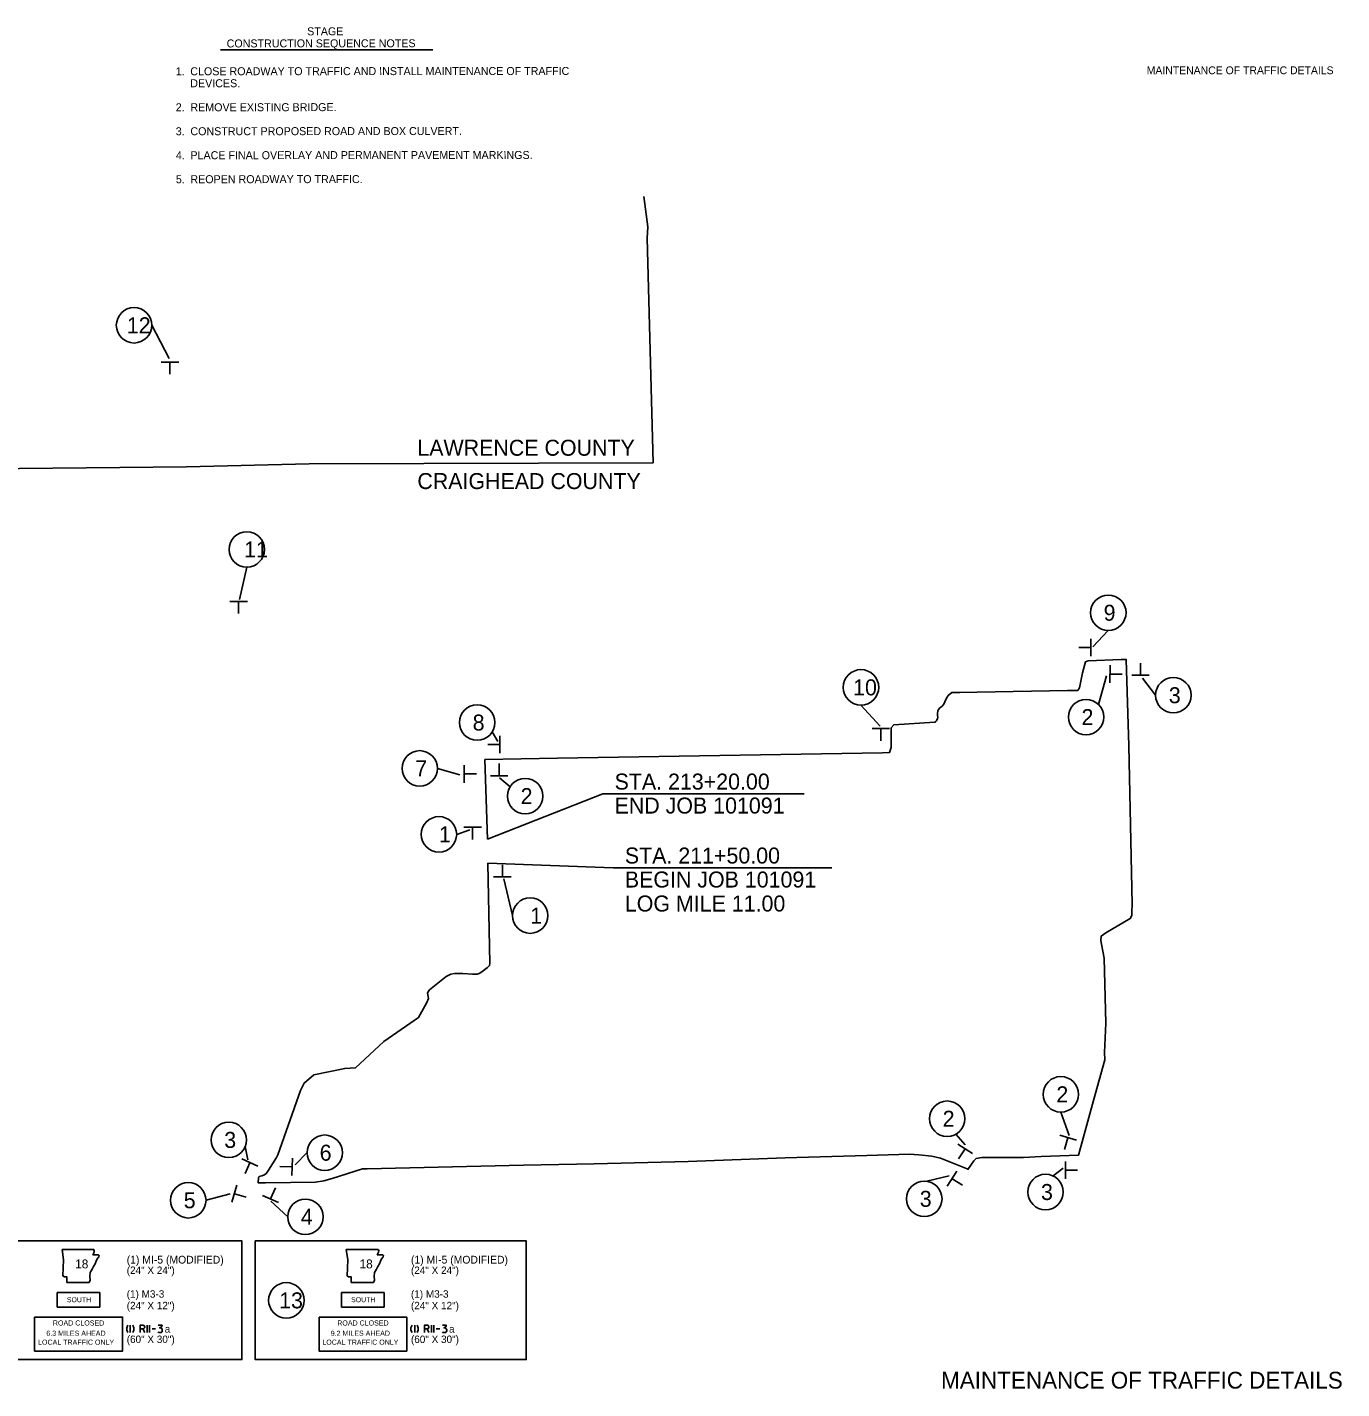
# Model space of a CAD drawing. Extents: x -31818 to 1228740, y -23925 to 152440.
# Drawn here: x -31762.5 to -31663.9, y -23925.5 to -23823.3 of the extents above; entities that cross this region are included whole.
import ezdxf

# ---------------------------------------------------------------- set-up
doc = ezdxf.new("R2010")
doc.units = 0
for name, color, linetype in [('2', 7, 'Continuous'), ('21', 7, 'Continuous'), ('3', 7, 'Continuous'), ('38', 7, 'Continuous'), ('53', 7, 'Continuous'), ('59', 7, 'Continuous'), ('8', 7, 'Continuous'), ('Level 1', 7, 'Continuous'), ('Level 3', 7, 'Continuous'), ('Level 8', 7, 'Continuous'), ('shading', 7, 'Continuous')]:
    doc.layers.add(name, color=color, linetype=linetype)

msp = doc.modelspace()

# ---------------------------------------------------------------- linework, layer by layer
at = {"layer": '21'}
for points in [[(-31759.89, -23915.04), (-31759.78, -23915.83), (-31759.83, -23917.03), (-31759.72, -23917.1), (-31759.53, -23917.1), (-31759.53, -23917.52), (-31757.86, -23917.52), (-31757.78, -23917.35), (-31757.81, -23917.07), (-31757.77, -23916.76), (-31757.63, -23916.51), (-31757.53, -23916.32), (-31757.4, -23916.12), (-31757.32, -23915.91), (-31757.25, -23915.74), (-31757.14, -23915.6), (-31757.11, -23915.5), (-31757.16, -23915.44), (-31757.57, -23915.44), (-31757.48, -23915.25), (-31757.47, -23915.13), (-31757.52, -23915.04)], [(-31738.56, -23915.04), (-31738.44, -23915.83), (-31738.49, -23917.03), (-31738.39, -23917.1), (-31738.19, -23917.1), (-31738.19, -23917.52), (-31736.53, -23917.52), (-31736.45, -23917.35), (-31736.48, -23917.07), (-31736.44, -23916.76), (-31736.29, -23916.51), (-31736.2, -23916.32), (-31736.07, -23916.12), (-31735.99, -23915.91), (-31735.92, -23915.74), (-31735.8, -23915.6), (-31735.77, -23915.5), (-31735.83, -23915.44), (-31736.24, -23915.44), (-31736.14, -23915.25), (-31736.13, -23915.13), (-31736.18, -23915.04)]]:
    msp.add_lwpolyline(points, close=True, dxfattribs=at)
at = {"layer": '53'}
for p, q in [((-31748, -23825.03), (-31732.07, -23825.03)), ((-31727.97, -23884.24), (-31719.32, -23880.86)), ((-31719.32, -23880.86), (-31704.2, -23880.86)), ((-31727.93, -23886.06), (-31718.54, -23886.41)), ((-31718.54, -23886.41), (-31702.12, -23886.41))]:
    msp.add_line(p, q, dxfattribs=at)
at = {"layer": '59'}
for p, q in [((-31757.05, -23918.27), (-31760.25, -23918.27)), ((-31760.25, -23918.27), (-31760.25, -23919.36)), ((-31757.05, -23918.27), (-31757.05, -23919.36)), ((-31735.71, -23918.27), (-31738.91, -23918.27)), ((-31738.91, -23918.27), (-31738.91, -23919.36)), ((-31735.71, -23918.27), (-31735.71, -23919.36)), ((-31757.05, -23919.36), (-31760.25, -23919.36)), ((-31735.71, -23919.36), (-31738.91, -23919.36))]:
    msp.add_line(p, q, dxfattribs=at)
at = {"layer": '8'}
for p, q in [((-31753.15, -23845.69), (-31751.86, -23848.18)), ((-31746.03, -23863.85), (-31746.57, -23866.27)), ((-31681.38, -23868.59), (-31682.54, -23869.81)), ((-31682.11, -23874.15), (-31681.52, -23872)), ((-31677.83, -23873.45), (-31678.82, -23872.17)), ((-31699.94, -23874.19), (-31698.49, -23875.78)), ((-31727.61, -23876.21), (-31727.18, -23876.92)), ((-31731.71, -23878.94), (-31730.05, -23879.42)), ((-31726.27, -23880.32), (-31727.06, -23879.64)), ((-31730.27, -23883.89), (-31729.28, -23883.55)), ((-31726.09, -23889.99), (-31726.74, -23887.24)), ((-31684.94, -23904.73), (-31684.31, -23906.49)), ((-31692.81, -23906.39), (-31692.12, -23907.18)), ((-31746.14, -23907.32), (-31745.95, -23908.31)), ((-31741.52, -23907.78), (-31742.41, -23908.68)), ((-31685.53, -23909.52), (-31684.76, -23908.93)), ((-31695, -23909.92), (-31693.33, -23909.51)), ((-31749.09, -23911.35), (-31747.27, -23910.87)), ((-31742.96, -23912.59), (-31744.23, -23911.42))]:
    msp.add_line(p, q, dxfattribs=at)
for points in [[(-31787.28, -23856.65), (-31787.2, -23856.65), (-31787.2, -23856.65), (-31782.9, -23856.63), (-31778.14, -23856.59), (-31750.55, -23856.3), (-31741.34, -23856.09), (-31715.54, -23856), (-31715.99, -23839.15), (-31715.94, -23838.29), (-31716.23, -23836.03)], [(-31727.93, -23886.06), (-31727.8, -23893.59), (-31727.82, -23893.72), (-31727.97, -23893.87), (-31728.4, -23894.21), (-31728.6, -23894.33), (-31728.75, -23894.37), (-31729.09, -23894.38), (-31729.81, -23894.34), (-31730.19, -23894.32), (-31730.44, -23894.32), (-31730.71, -23894.37), (-31731.07, -23894.56), (-31732.33, -23895.56), (-31732.47, -23895.78), (-31732.4, -23896.21), (-31732.52, -23896.5), (-31733.14, -23897.63), (-31735.74, -23899.44), (-31737.88, -23901.41), (-31738.68, -23901.45), (-31741, -23901.94), (-31741.72, -23902.55), (-31742, -23903.11), (-31743.71, -23907.94), (-31743.8, -23908.13), (-31744.4, -23909.1), (-31744.55, -23909.32), (-31744.69, -23909.45), (-31744.9, -23909.51), (-31745.1, -23909.57), (-31745.15, -23909.67), (-31745.18, -23910.04), (-31744.63, -23910.04), (-31740.87, -23909.98), (-31740.25, -23909.88), (-31739.63, -23909.72), (-31737.35, -23908.98), (-31737, -23908.98), (-31725.27, -23908.72), (-31719.95, -23908.62), (-31712.9, -23908.44), (-31705.62, -23908.16), (-31699.51, -23907.98), (-31696.31, -23907.88), (-31695.61, -23907.94), (-31694.63, -23908.05), (-31693.98, -23908.2), (-31691.96, -23909), (-31691.91, -23909.04), (-31691.46, -23908.39), (-31691.3, -23908.21), (-31690.86, -23908.13), (-31687.75, -23908.15), (-31686.43, -23908.07), (-31683.61, -23907.96), (-31682.49, -23903.86), (-31681.65, -23900.8), (-31681.66, -23900.25), (-31681.56, -23898.07), (-31681.7, -23893.18), (-31681.89, -23892.12), (-31681.93, -23891.85), (-31681.91, -23891.53), (-31681.56, -23891.28), (-31679.74, -23890.21), (-31679.62, -23889.97), (-31679.62, -23889.73), (-31679.59, -23889.12), (-31679.85, -23877.26), (-31680.03, -23870.76), (-31680.42, -23870.78), (-31682.88, -23870.87), (-31683.09, -23870.94), (-31683.31, -23871.76), (-31683.55, -23872.9), (-31683.67, -23873.09), (-31684.44, -23873.09), (-31691.22, -23873.21), (-31692.51, -23873.25), (-31693.12, -23873.25), (-31693.39, -23873.48), (-31693.52, -23873.68), (-31693.66, -23873.94), (-31693.72, -23874.12), (-31693.86, -23874.27), (-31694.05, -23874.41), (-31694.16, -23874.56), (-31694.17, -23874.62), (-31694.2, -23874.81), (-31694.19, -23874.9), (-31694.19, -23874.98), (-31694.18, -23875.1), (-31694.21, -23875.23), (-31694.24, -23875.3), (-31694.27, -23875.37), (-31694.35, -23875.45), (-31694.39, -23875.48), (-31697.48, -23875.67), (-31697.67, -23875.89), (-31697.68, -23877.38), (-31697.81, -23877.76), (-31698.33, -23877.77), (-31707.49, -23877.92), (-31722.71, -23878.18), (-31728.16, -23878.28), (-31727.97, -23884.24)]]:
    msp.add_lwpolyline(points, dxfattribs=at)
for points in [[(-31766.73, -23914.4), (-31746.4, -23914.4), (-31746.4, -23923.31), (-31766.73, -23923.31)], [(-31745.4, -23914.4), (-31725.06, -23914.4), (-31725.06, -23923.31), (-31745.4, -23923.31)]]:
    msp.add_lwpolyline(points, close=True, dxfattribs=at)
at = {"layer": 'Level 1'}
for points in [[(-31761.95, -23920.11), (-31755.35, -23920.11), (-31755.35, -23922.67), (-31761.95, -23922.67)], [(-31740.61, -23920.11), (-31734.02, -23920.11), (-31734.02, -23922.67), (-31740.61, -23922.67)]]:
    msp.add_lwpolyline(points, close=True, dxfattribs=at)
at = {"layer": 'Level 3'}
for p, q in [((-31752.45, -23848.45), (-31751.14, -23848.45)), ((-31751.8, -23848.47), (-31751.8, -23849.36)), ((-31747.29, -23866.41), (-31745.98, -23866.41)), ((-31746.64, -23866.43), (-31746.64, -23867.32)), ((-31682.71, -23869.87), (-31683.6, -23869.87)), ((-31682.69, -23869.22), (-31682.69, -23870.53)), ((-31681.26, -23872.51), (-31681.25, -23871.2)), ((-31678.96, -23871.93), (-31678.96, -23871.04)), ((-31681.24, -23871.86), (-31680.34, -23871.86)), ((-31678.31, -23871.95), (-31679.62, -23871.95)), ((-31699.11, -23875.95), (-31697.8, -23875.95)), ((-31698.46, -23875.97), (-31698.46, -23876.87)), ((-31727.05, -23877.14), (-31727.95, -23877.14)), ((-31727.03, -23876.49), (-31727.03, -23877.8)), ((-31729.71, -23880.02), (-31729.72, -23878.7)), ((-31729.69, -23879.36), (-31728.8, -23879.35)), ((-31727.08, -23879.47), (-31727.08, -23878.58)), ((-31726.43, -23879.49), (-31727.74, -23879.49)), ((-31729.73, -23883.35), (-31728.42, -23883.35)), ((-31729.08, -23883.37), (-31729.08, -23884.27)), ((-31726.85, -23887.08), (-31726.85, -23886.18)), ((-31726.2, -23887.09), (-31727.51, -23887.09)), ((-31685.03, -23906.47), (-31683.77, -23906.84)), ((-31684.41, -23906.67), (-31684.66, -23907.53)), ((-31692.67, -23907.13), (-31691.56, -23907.84)), ((-31692.13, -23907.5), (-31692.61, -23908.25)), ((-31746.39, -23908.25), (-31745.19, -23908.78)), ((-31745.8, -23908.53), (-31746.16, -23909.35)), ((-31742.64, -23908.83), (-31743.54, -23908.81)), ((-31742.61, -23908.18), (-31742.64, -23909.49)), ((-31684.6, -23909.74), (-31684.6, -23908.43)), ((-31693.46, -23910.28), (-31692.75, -23909.17)), ((-31693.09, -23909.74), (-31692.33, -23910.22)), ((-31684.58, -23909.09), (-31683.69, -23909.09)), ((-31747.15, -23911.48), (-31746.77, -23910.22)), ((-31746.94, -23910.86), (-31746.08, -23911.12)), ((-31743.65, -23911.52), (-31744.85, -23910.99)), ((-31744.24, -23911.24), (-31743.88, -23910.42))]:
    msp.add_line(p, q, dxfattribs=at)
at = {"layer": 'Level 8'}
for p, q in [((-31754.77, -23921.28), (-31754.77, -23920.73)), ((-31753.82, -23921), (-31753.69, -23921.28)), ((-31753.51, -23921.28), (-31753.51, -23920.73)), ((-31753.33, -23921.28), (-31753.33, -23920.73)), ((-31753.14, -23921), (-31752.87, -23921)), ((-31733.43, -23921.28), (-31733.43, -23920.73)), ((-31732.49, -23921), (-31732.36, -23921.28)), ((-31732.18, -23921.28), (-31732.18, -23920.73)), ((-31731.99, -23921.28), (-31731.99, -23920.73)), ((-31731.81, -23921), (-31731.54, -23921))]:
    msp.add_line(p, q, dxfattribs=at)
for points in [[(-31754.95, -23920.73), (-31755.04, -23920.91), (-31755.04, -23921.1), (-31754.95, -23921.28)], [(-31754.59, -23920.73), (-31754.5, -23920.91), (-31754.5, -23921.1), (-31754.59, -23921.28)], [(-31754.04, -23921.28), (-31754.04, -23920.73), (-31753.82, -23920.73), (-31753.75, -23920.75), (-31753.69, -23920.84), (-31753.69, -23920.89), (-31753.75, -23920.98), (-31753.82, -23921), (-31754.04, -23921)], [(-31752.69, -23920.73), (-31752.39, -23920.73), (-31752.41, -23920.79), (-31752.44, -23920.84), (-31752.48, -23920.88), (-31752.57, -23920.93), (-31752.51, -23920.93), (-31752.44, -23920.96), (-31752.39, -23921), (-31752.37, -23921.07), (-31752.37, -23921.15), (-31752.39, -23921.22), (-31752.44, -23921.27), (-31752.51, -23921.28), (-31752.58, -23921.28), (-31752.65, -23921.27), (-31752.69, -23921.22)], [(-31733.62, -23920.73), (-31733.71, -23920.91), (-31733.71, -23921.1), (-31733.62, -23921.28)], [(-31733.25, -23920.73), (-31733.16, -23920.91), (-31733.16, -23921.1), (-31733.25, -23921.28)], [(-31732.7, -23921.28), (-31732.7, -23920.73), (-31732.48, -23920.73), (-31732.41, -23920.75), (-31732.36, -23920.84), (-31732.36, -23920.89), (-31732.41, -23920.98), (-31732.48, -23921), (-31732.7, -23921)], [(-31731.35, -23920.73), (-31731.06, -23920.73), (-31731.07, -23920.79), (-31731.1, -23920.84), (-31731.15, -23920.88), (-31731.24, -23920.93), (-31731.17, -23920.93), (-31731.1, -23920.96), (-31731.06, -23921), (-31731.03, -23921.07), (-31731.03, -23921.15), (-31731.06, -23921.22), (-31731.1, -23921.27), (-31731.17, -23921.28), (-31731.25, -23921.28), (-31731.31, -23921.27), (-31731.35, -23921.22)]]:
    msp.add_lwpolyline(points, dxfattribs=at)
for centre in [(-31754.49, -23845.69), (-31746.03, -23862.51), (-31681.38, -23867.26), (-31699.94, -23872.86), (-31676.5, -23873.45), (-31728.74, -23875.5), (-31683.05, -23875.09), (-31733.05, -23878.94), (-31725.14, -23881.02), (-31731.61, -23883.89), (-31724.76, -23889.99), (-31684.94, -23903.4), (-31693.47, -23905.23), (-31747.38, -23906.82), (-31740.18, -23907.78), (-31750.42, -23911.35), (-31695.19, -23911.24), (-31686.09, -23910.73), (-31741.63, -23912.59), (-31743.06, -23918.86)]:
    msp.add_circle(centre, 1.33, dxfattribs=at)
at = {"layer": 'shading'}
for centre in [(-31754.49, -23845.69), (-31746.03, -23862.51), (-31681.38, -23867.26), (-31699.94, -23872.86), (-31676.5, -23873.45), (-31728.74, -23875.5), (-31683.05, -23875.09), (-31733.05, -23878.94), (-31725.14, -23881.02), (-31731.61, -23883.89), (-31724.76, -23889.99), (-31684.94, -23903.4), (-31693.47, -23905.23), (-31747.38, -23906.82), (-31740.18, -23907.78), (-31750.42, -23911.35), (-31695.19, -23911.24), (-31686.09, -23910.73), (-31741.63, -23912.59), (-31743.06, -23918.86)]:
    msp.add_circle(centre, 1.33, dxfattribs=at)

# ---------------------------------------------------------------- texts
at = {"layer": '2'}
msp.add_text('MAINTENANCE OF TRAFFIC DETAILS', height=0.5862, dxfattribs=at).set_placement((-31678.5, -23826.85))
at = {"layer": '3'}
for p in [(-31759.53, -23919), (-31738.2, -23919)]:
    msp.add_text('SOUTH', height=0.376, rotation=360, dxfattribs=at).set_placement(p)
at = {"layer": '38'}
msp.add_text('MAINTENANCE OF TRAFFIC DETAILS', height=1.26, dxfattribs=at).set_placement((-31693.93, -23925.48))
at = {"layer": '53'}
for s, height, rotation, p in [('STAGE', 0.6, 0.0508, (-31741.5, -23823.93)), ('CONSTRUCTION SEQUENCE NOTES', 0.6, 0.0508, (-31747.54, -23824.84)), ('1.', 0.6, 0.0508, (-31751.36, -23826.93)), ('CLOSE ROADWAY TO TRAFFIC AND INSTALL MAINTENANCE OF TRAFFIC ', 0.6, 0.0508, (-31750.27, -23826.93)), ('DEVICES. ', 0.6, 0.0508, (-31750.27, -23827.83)), ('2.', 0.6, 0.0508, (-31751.36, -23829.63)), ('REMOVE EXISTING BRIDGE.', 0.6, 0.0508, (-31750.26, -23829.63)), ('3.', 0.6, 0.0508, (-31751.36, -23831.43)), ('CONSTRUCT PROPOSED ROAD AND BOX CULVERT.', 0.6, 0.0508, (-31750.26, -23831.43)), ('4.', 0.6, 0.0508, (-31751.35, -23833.23)), ('PLACE FINAL OVERLAY AND PERMANENT PAVEMENT MARKINGS.', 0.6, 0.0508, (-31750.26, -23833.23)), ('REOPEN ROADWAY TO TRAFFIC.', 0.6, 0.0508, (-31750.26, -23835.03)), ('5.', 0.6, 0.0508, (-31751.35, -23835.03)), ('LAWRENCE COUNTY', 1.2, 0, (-31733.23, -23855.48)), ('CRAIGHEAD COUNTY', 1.2, 0, (-31733.23, -23857.98)), ('STA. 213+20.00', 1.2, 0, (-31718.43, -23880.53)), ('END JOB 101091', 1.2, 0, (-31718.43, -23882.33)), ('STA. 211+50.00', 1.2, 0, (-31717.66, -23886.08)), ('BEGIN JOB 101091', 1.2, 0, (-31717.66, -23887.88)), ('LOG MILE 11.00', 1.2, 0, (-31717.66, -23889.68))]:
    msp.add_text(s, height=height, rotation=rotation, dxfattribs=at).set_placement(p)
at = {"layer": '8'}
for p in [(-31758.91, -23916.46), (-31737.57, -23916.46)]:
    msp.add_text('18', height=0.667, dxfattribs=at).set_placement(p)
at = {"layer": 'Level 1'}
for s, p in [('6.3 MILES AHEAD', (-31761.07, -23921.52)), ('9.2 MILES AHEAD', (-31739.73, -23921.52))]:
    msp.add_text(s, height=0.3836, dxfattribs=at).set_placement(p)
at = {"layer": 'Level 3'}
for s, p in [('ROAD CLOSED', (-31760.58, -23920.75)), ('ROAD CLOSED', (-31739.24, -23920.75)), ('LOCAL TRAFFIC ONLY', (-31761.69, -23922.19)), ('LOCAL TRAFFIC ONLY', (-31740.36, -23922.19))]:
    msp.add_text(s, height=0.3836, dxfattribs=at).set_placement(p)
at = {"layer": 'Level 8'}
for s, height, p in [('12', 1.2, (-31755.03, -23846.29)), ('11', 1.2, (-31746.23, -23863.11)), ('9', 1.2, (-31681.73, -23867.86)), ('10', 1.2, (-31700.53, -23873.46)), ('3', 1.2, (-31676.84, -23874.05)), ('8', 1.2, (-31729.08, -23876.1)), ('2', 1.2, (-31683.39, -23875.69)), ('7', 1.2, (-31733.39, -23879.54)), ('2', 1.2, (-31725.48, -23881.62)), ('1', 1.2, (-31731.61, -23884.49)), ('1', 1.2, (-31724.76, -23890.59)), ('2', 1.2, (-31685.28, -23904)), ('2', 1.2, (-31693.81, -23905.83)), ('3', 1.2, (-31747.72, -23907.42)), ('6', 1.2, (-31740.56, -23908.38)), ('5', 1.2, (-31750.76, -23911.95)), ('3', 1.2, (-31695.53, -23911.84)), ('3', 1.2, (-31686.43, -23911.33)), ('4', 1.2, (-31741.97, -23913.19)), ('13', 1.2, (-31743.6, -23919.46)), ('a', 0.558, (-31752.19, -23921.28)), ('a', 0.558, (-31730.85, -23921.28)), ('(60" X 30")', 0.5583, (-31755.04, -23922.06)), ('(60" X 30")', 0.5583, (-31733.71, -23922.06))]:
    msp.add_text(s, height=height, dxfattribs=at).set_placement(p)
for s, height, rotation, p in [('(1) MI-5 (MODIFIED)', 0.5833, 360, (-31755.04, -23916.1)), ('(1) MI-5 (MODIFIED)', 0.5833, 360, (-31733.71, -23916.1)), ('(24" X 24")', 0.5583, 0, (-31755.04, -23916.88)), ('(24" X 24")', 0.5583, 0, (-31733.71, -23916.88)), ('(1) M3-3', 0.558, 0, (-31755.04, -23918.66)), ('(1) M3-3', 0.558, 0, (-31733.71, -23918.66)), ('(24" X 12")', 0.5583, 0, (-31755.04, -23919.53)), ('(24" X 12")', 0.5583, 0, (-31733.71, -23919.53))]:
    msp.add_text(s, height=height, rotation=rotation, dxfattribs=at).set_placement(p)

doc.saveas('drawing.dxf')
